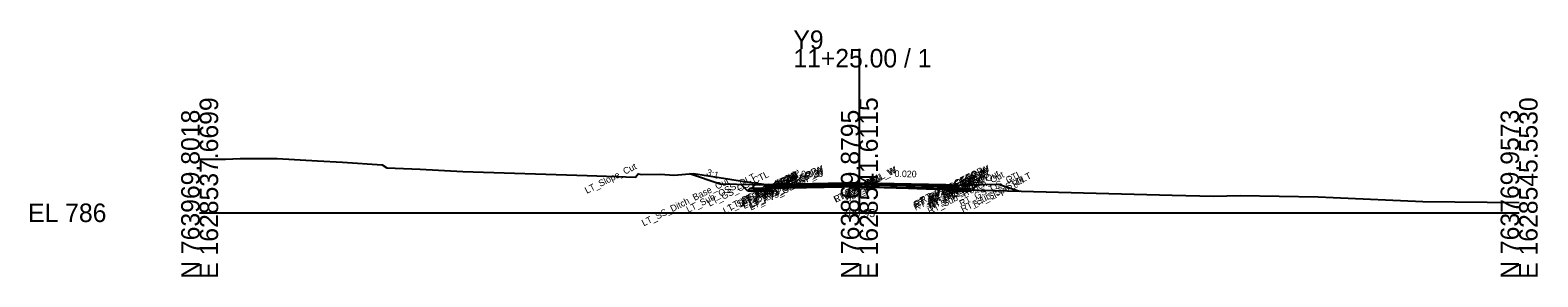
# Model space of a CAD drawing. Extents: x -26 to 203, y -10 to 6017.
# Drawn here: x -25.7 to 202.8, y 2490.3 to 2527.6 of the extents above; entities that cross this region are included whole.
import ezdxf

# ---------------------------------------------------------------- set-up
doc = ezdxf.new("R2010")
doc.units = 0
for name, color, linetype in [('Default', 7, 'Continuous'), ('Exist Cross Section Cell', 7, 'Continuous'), ('Exist XS Center Line Elevation Label', 7, 'Continuous'), ('Exist XS Ground Line', 7, 'Continuous'), ('Prop CMT Concrete Structures', 7, 'Continuous'), ('Prop CMT Pvmt Course 1', 7, 'Continuous'), ('Prop CMT Pvmt Course 1 Wedge', 7, 'Continuous'), ('Prop CMT Pvmt Course 2', 7, 'Continuous'), ('Prop CMT Pvmt Course 2 Wedge', 7, 'Continuous'), ('Prop CMT Pvmt Course 3', 7, 'Continuous'), ('Prop CMT Pvmt Course 3 Wedge', 7, 'Continuous'), ('Prop CMT Pvmt Surface', 7, 'Continuous'), ('Prop CMT Pvmt Surface Shoulder', 7, 'Continuous'), ('Prop CMT Pvmt Wedge Surface 1', 7, 'Continuous'), ('Prop CMT Pvmt Wedge Surface 2', 7, 'Continuous'), ('Prop CMT Pvmt Wedge Surface 3', 7, 'Continuous'), ('Prop CMT Shld Paved Course 1', 7, 'Continuous'), ('Prop CMT Shld Paved Course 2', 7, 'Continuous'), ('Prop CMT Shld Paved Course 3', 7, 'Continuous'), ('Prop CMT Slope Grass', 7, 'Continuous'), ('Prop CMT Subgrade Earthwork', 7, 'Continuous'), ('Prop XS SE Text', 7, 'Continuous'), ('Prop XS Side Slope Text', 7, 'Continuous'), ('Scratch_Level_0', 7, 'Continuous')]:
    doc.layers.add(name, color=color, linetype=linetype)

msp = doc.modelspace()

# ---------------------------------------------------------------- linework, layer by layer
at = {"layer": 'Exist Cross Section Cell'}
for p, q in [((100, 2500), (100, 2524.81)), ((0, 2500), (100, 2500)), ((100, 2500), (200, 2500))]:
    msp.add_line(p, q, dxfattribs=at)
at = {"layer": 'Exist XS Ground Line'}
msp.add_lwpolyline([(0, 2508.13), (3.93, 2508.14), (6.13, 2508.23), (8.45, 2508.23), (11.76, 2508.23), (17.85, 2507.85), (21.65, 2507.66), (27.67, 2507.27), (28.35, 2506.83), (33.42, 2506.59), (39.89, 2506.24), (58.74, 2505.65), (66.06, 2505.41), (66.47, 2505.91), (66.99, 2505.81), (69.85, 2505.86), (71.89, 2505.71), (74.88, 2505.94), (76.18, 2505.75), (80.36, 2505.1), (82.21, 2504.81), (85.88, 2504.28), (86.65, 2503.84), (93.47, 2503.9), (98.86, 2503.98), (100, 2503.95), (107.43, 2503.73), (114.09, 2503.49), (114.47, 2503.57), (115.88, 2503.5), (120.36, 2503.4), (124.52, 2503.3), (133.95, 2503.01), (147.39, 2502.66), (153.68, 2502.51), (157.73, 2502.61), (169.53, 2502.44), (171.83, 2502.3), (185.41, 2501.72), (200, 2501.57)], dxfattribs=at)
at = {"layer": 'Prop CMT Concrete Structures'}
for points in [[(83.9, 2504.25), (83.9, 2503.67), (85.9, 2503.67)], [(85.9, 2504.25), (84.9, 2504.17), (83.9, 2504.25)], [(85.9, 2503.67), (85.9, 2504.25)], [(116.1, 2504.25), (116.1, 2503.67), (114.1, 2503.67)], [(114.1, 2504.25), (115.1, 2504.17), (116.1, 2504.25)], [(114.1, 2503.67), (114.1, 2504.25)]]:
    msp.add_lwpolyline(points, dxfattribs=at)
at = {"layer": 'Prop CMT Pvmt Course 1'}
for points in [[(100, 2504.54), (85.9, 2504.25)], [(85.9, 2504), (100, 2504.29)], [(85.9, 2504.25), (85.9, 2504)], [(86.65, 2504.14), (100, 2504.41)], [(86.65, 2504.27), (86.65, 2504.14)], [(100, 2504.54), (88.11, 2504.3)], [(100, 2504.41), (100, 2504.54)], [(100, 2504.29), (100, 2504.54)], [(100, 2504.54), (113.1, 2504.27)], [(100, 2504.41), (100, 2504.54)], [(100, 2504.54), (114.1, 2504.25)], [(100, 2504.29), (100, 2504.54)], [(113.1, 2504.15), (100, 2504.41)], [(114.1, 2504), (100, 2504.29)], [(113.1, 2504.27), (113.1, 2504.15)], [(114.1, 2504.25), (114.1, 2504)]]:
    msp.add_lwpolyline(points, dxfattribs=at)
at = {"layer": 'Prop CMT Pvmt Course 1 Wedge'}
for points in [[(86.65, 2504.02), (86.65, 2504.14)], [(88.11, 2504.17), (93.47, 2504.28), (98.86, 2504.39), (100, 2504.41)], [(100, 2504.29), (98.86, 2504.26), (93.47, 2504.16), (88.11, 2504.05)], [(100, 2504.41), (100, 2504.29)], [(100, 2504.41), (107.43, 2504.26), (113.1, 2504.15)], [(100, 2504.29), (100, 2504.41)], [(113.1, 2504.02), (107.43, 2504.14), (100, 2504.29)], [(113.1, 2504.15), (113.1, 2504.02)]]:
    msp.add_lwpolyline(points, dxfattribs=at)
at = {"layer": 'Prop CMT Pvmt Course 2'}
for points in [[(100, 2504.29), (85.9, 2504)], [(85.9, 2504), (85.9, 2503.67)], [(85.9, 2503.67), (86.65, 2503.69)], [(100, 2503.95), (100, 2504.29)], [(100, 2503.95), (100, 2504.29)], [(100, 2504.29), (114.1, 2504)], [(114.1, 2503.67), (100, 2503.95)], [(114.1, 2504), (114.1, 2503.67)]]:
    msp.add_lwpolyline(points, dxfattribs=at)
at = {"layer": 'Prop CMT Pvmt Course 2 Wedge'}
for points in [[(86.65, 2503.83), (86.65, 2504.02)], [(88.11, 2504.05), (93.47, 2504.16), (98.86, 2504.26), (100, 2504.29)], [(100, 2503.95), (99.93, 2503.95), (98.86, 2503.98), (93.47, 2503.9), (88.11, 2503.86)], [(100, 2504.29), (100, 2503.95)], [(100, 2504.29), (107.43, 2504.14), (113.1, 2504.02)], [(100, 2503.95), (100, 2504.29)], [(113.1, 2503.69), (107.43, 2503.8), (100, 2503.95)], [(113.1, 2504.02), (113.1, 2503.69)]]:
    msp.add_lwpolyline(points, dxfattribs=at)
at = {"layer": 'Prop CMT Pvmt Course 3'}
msp.add_line((116.1, 2503.67), (116.6, 2503.67), dxfattribs=at)
for points in [[(86.65, 2503.69), (85.9, 2503.67)], [(85.9, 2503.67), (85.9, 2503.34)], [(85.9, 2503.34), (86.65, 2503.35)], [(100, 2503.95), (114.1, 2503.67)], [(114.1, 2503.34), (113.1, 2503.36)], [(114.1, 2503.67), (114.1, 2503.34)]]:
    msp.add_lwpolyline(points, dxfattribs=at)
at = {"layer": 'Prop CMT Pvmt Course 3 Wedge'}
for points in [[(100, 2503.95), (99.93, 2503.95)], [(99.93, 2503.95), (100, 2503.95)], [(100, 2503.95), (100, 2503.95)], [(100, 2503.95), (107.43, 2503.8), (113.1, 2503.69)], [(113.1, 2503.53), (107.43, 2503.73), (100, 2503.95)], [(100, 2503.95), (100, 2503.95)], [(113.1, 2503.69), (113.1, 2503.53)]]:
    msp.add_lwpolyline(points, dxfattribs=at)
at = {"layer": 'Prop CMT Pvmt Surface'}
for points in [[(100, 2504.54), (85.9, 2504.25)], [(100, 2504.54), (88.11, 2504.3)], [(100, 2504.54), (114.1, 2504.25)], [(100, 2504.54), (113.1, 2504.27)]]:
    msp.add_lwpolyline(points, dxfattribs=at)
at = {"layer": 'Prop CMT Pvmt Surface Shoulder'}
for points in [[(85.9, 2504.25), (85.9, 2504.25)], [(114.1, 2504.25), (114.1, 2504.25)]]:
    msp.add_lwpolyline(points, dxfattribs=at)
at = {"layer": 'Prop CMT Pvmt Wedge Surface 1'}
for points in [[(86.65, 2504.14), (86.65, 2504.27)], [(100, 2504.41), (88.11, 2504.17)], [(100, 2504.41), (113.1, 2504.15)], [(113.1, 2504.15), (113.1, 2504.27)]]:
    msp.add_lwpolyline(points, dxfattribs=at)
at = {"layer": 'Prop CMT Pvmt Wedge Surface 2'}
for points in [[(86.65, 2504.02), (86.65, 2504.27)], [(100, 2504.29), (88.11, 2504.05)], [(100, 2504.29), (100, 2504.54)], [(100, 2504.29), (100, 2504.54)], [(100, 2504.29), (100, 2504.54)], [(100, 2504.29), (100, 2504.54)], [(100, 2504.29), (113.1, 2504.02)], [(113.1, 2504.02), (113.1, 2504.27)]]:
    msp.add_lwpolyline(points, dxfattribs=at)
at = {"layer": 'Prop CMT Pvmt Wedge Surface 3'}
for points in [[(86.65, 2503.69), (86.65, 2504.27)], [(100, 2503.95), (86.65, 2503.69)], [(100, 2503.95), (100, 2504.54)], [(100, 2503.95), (100, 2504.54)], [(100, 2503.95), (100, 2504.54)], [(100, 2503.95), (100, 2504.54)], [(100, 2503.95), (113.1, 2503.69)], [(113.1, 2503.69), (113.1, 2504.27)]]:
    msp.add_lwpolyline(points, dxfattribs=at)
at = {"layer": 'Prop CMT Shld Paved Course 1'}
for points in [[(85.9, 2504.25), (85.9, 2504.25)], [(85.9, 2504), (85.9, 2504.25)], [(114.1, 2504.25), (114.1, 2504.25)], [(114.1, 2504), (114.1, 2504.25)]]:
    msp.add_lwpolyline(points, dxfattribs=at)
at = {"layer": 'Prop CMT Shld Paved Course 2'}
for p, q in [((83.9, 2503.67), (85.9, 2503.67)), ((116.1, 2503.67), (114.1, 2503.67))]:
    msp.add_line(p, q, dxfattribs=at)
for points in [[(85.9, 2503.67), (85.9, 2504)], [(114.1, 2503.67), (114.1, 2504)]]:
    msp.add_lwpolyline(points, dxfattribs=at)
at = {"layer": 'Prop CMT Shld Paved Course 3'}
for p, q in [((83.06, 2503.33), (85.9, 2503.34)), ((116.94, 2503.33), (114.1, 2503.34))]:
    msp.add_line(p, q, dxfattribs=at)
for points in [[(85.9, 2503.67), (83.9, 2503.67), (83.4, 2503.67), (83.06, 2503.33)], [(85.9, 2503.34), (85.9, 2503.67)], [(114.1, 2503.34), (114.1, 2503.67)], [(114.1, 2503.67), (116.6, 2503.67), (116.6, 2503.67), (116.94, 2503.33)]]:
    msp.add_lwpolyline(points, dxfattribs=at)
at = {"layer": 'Prop CMT Slope Grass'}
for points in [[(83.9, 2504.25), (78.9, 2504.35), (74.27, 2505.9)], [(116.1, 2504.25), (121.1, 2504.35), (124.25, 2503.3)]]:
    msp.add_lwpolyline(points, dxfattribs=at)
at = {"layer": 'Prop CMT Subgrade Earthwork'}
for p, q in [((83.06, 2503.33), (82.1, 2504.29)), ((85.9, 2503.34), (83.06, 2503.33)), ((86.65, 2503.84), (86.65, 2503.35)), ((113.1, 2503.53), (113.1, 2503.36)), ((114.1, 2503.34), (116.94, 2503.33)), ((116.94, 2503.33), (117.9, 2504.29))]:
    msp.add_line(p, q, dxfattribs=at)
for points in [[(86.65, 2503.35), (85.9, 2503.34)], [(113.1, 2503.36), (114.1, 2503.34)]]:
    msp.add_lwpolyline(points, dxfattribs=at)

# ---------------------------------------------------------------- texts
at = {"layer": 'Default'}
msp.add_text('-', height=0.0001, dxfattribs=at).set_placement((0, 2500))
at = {"layer": 'Exist Cross Section Cell'}
for s, p in [('Y9', (90, 2524.81)), ('11+25.00 / 1', (90, 2522.01)), ('EL 786', (-26, 2498.6))]:
    msp.add_text(s, height=2.8, dxfattribs=at).set_placement(p)
for s, p in [('E 1628537.6699', (2.8, 2490)), ('E 1628541.6115', (102.8, 2490)), ('E 1628545.5530', (202.8, 2490)), ('N 763969.8018', (0, 2490)), ('N 763869.8795', (100, 2490)), ('N 763769.9573', (200, 2490))]:
    msp.add_text(s, height=2.8, rotation=90, dxfattribs=at).set_placement(p)
at = {"layer": 'Exist XS Center Line Elevation Label'}
msp.add_text('789.95', height=1.2, dxfattribs=at).set_placement((97.48, 2499.35))
at = {"layer": 'Prop XS SE Text'}
for rotation, p in [(1.1458, (91.18, 2505.36)), (358.8542, (105.32, 2505.43))]:
    msp.add_text('0.020', height=1, rotation=rotation, dxfattribs=at).set_placement(p)
at = {"layer": 'Prop XS Side Slope Text'}
for p in [(76.73, 2505.73), (122.26, 2504.71)]:
    msp.add_text('3:1', height=1, rotation=341.5651, dxfattribs=at).set_placement(p)
at = {"layer": 'Scratch_Level_0'}
for s, p in [('LT_Slope_Cut', (58.69, 2502.87)), ('LT_PV2_OEEOP_W', (83.58, 2500.66)), ('LT_PV1_OEEOP_W', (83.68, 2500.84)), ('RT_PV1_PGL_W', (96.41, 2501.5)), ('LT_PV1_PGL_W', (96.47, 2501.53)), ('RT_PV2_OEEOP_W', (108.52, 2500.61)), ('RT_PV1_OEEOP_W', (108.62, 2500.79)), ('LT_SS_Ditch_Base_Out', (67.32, 2497.94)), ('LT_Sub_OSS_DLT', (74.06, 2499.98)), ('LT_GS_OS_CTL', (77.29, 2500.93)), ('LT_Sub_Trench_Out', (79.64, 2499.78)), ('LT_PS3_Shelf_Out', (80.47, 2500.36)), ('LT_PS3_OEOP', (81.98, 2500.88)), ('LT_PS2_OEOP', (82.32, 2501.22)), ('LT_PV2_OEOT', (82.54, 2501.21)), ('LT_PV3_OEOT', (82.54, 2500.87)), ('LT_Sub_OEOT', (82.56, 2500.55)), ('LT_PV1_OEOT', (82.65, 2501.51)), ('LT_PS1_OEOP', (82.69, 2501.53)), ('LT_PV3_OEEOP_W', (83.58, 2500.33)), ('LT_PV1_OEEOP', (84.54, 2501.4)), ('PV2_PGL', (98.08, 2502.21)), ('PV3_PGL', (98.08, 2501.87)), ('Sub_PGL', (98.1, 2501.55)), ('PV1_PGL', (98.18, 2502.51)), ('RT_PV3_OEEOP_W', (108.52, 2500.28)), ('RT_PV1_OEEOP', (109.48, 2501.35)), ('RT_Sub_Trench_Out', (110.66, 2499.75)), ('RT_PV2_OEOT', (110.69, 2501.18)), ('RT_PV3_OEOT', (110.69, 2500.85)), ('RT_Sub_OEOT', (110.71, 2500.52)), ('RT_PV1_OEOT', (110.8, 2501.48)), ('RT_PS3_Shelf_Out', (110.81, 2500.34)), ('RT_PS1_OEOP', (110.83, 2501.5)), ('RT_PS2_OEOP', (110.98, 2501.19)), ('RT_PS3_OEOP', (111.32, 2500.85)), ('RT_GS_OS_CTL', (115.44, 2500.9)), ('RT_Sub_OSS_DLT', (115.68, 2500.04)), ('RT_Slope_Fill', (117.49, 2500.8))]:
    msp.add_text(s, height=1, rotation=26.5651, dxfattribs=at).set_placement(p)

doc.saveas('drawing.dxf')
